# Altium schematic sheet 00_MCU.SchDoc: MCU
size A3; Date: 3/31/2015; Author: P.A.; CompanyName: STMicroelectronics; Organization: Microcontrollers Division; Address1: 12, Rue Jules HOROWITZ; Address2: 38019 Grenoble; Address3: FRANCE; DocumentNumber: 3; Revision: E-01; SheetNumber: 3; SheetTotal: 12; Project: STM32F413H-DISCO
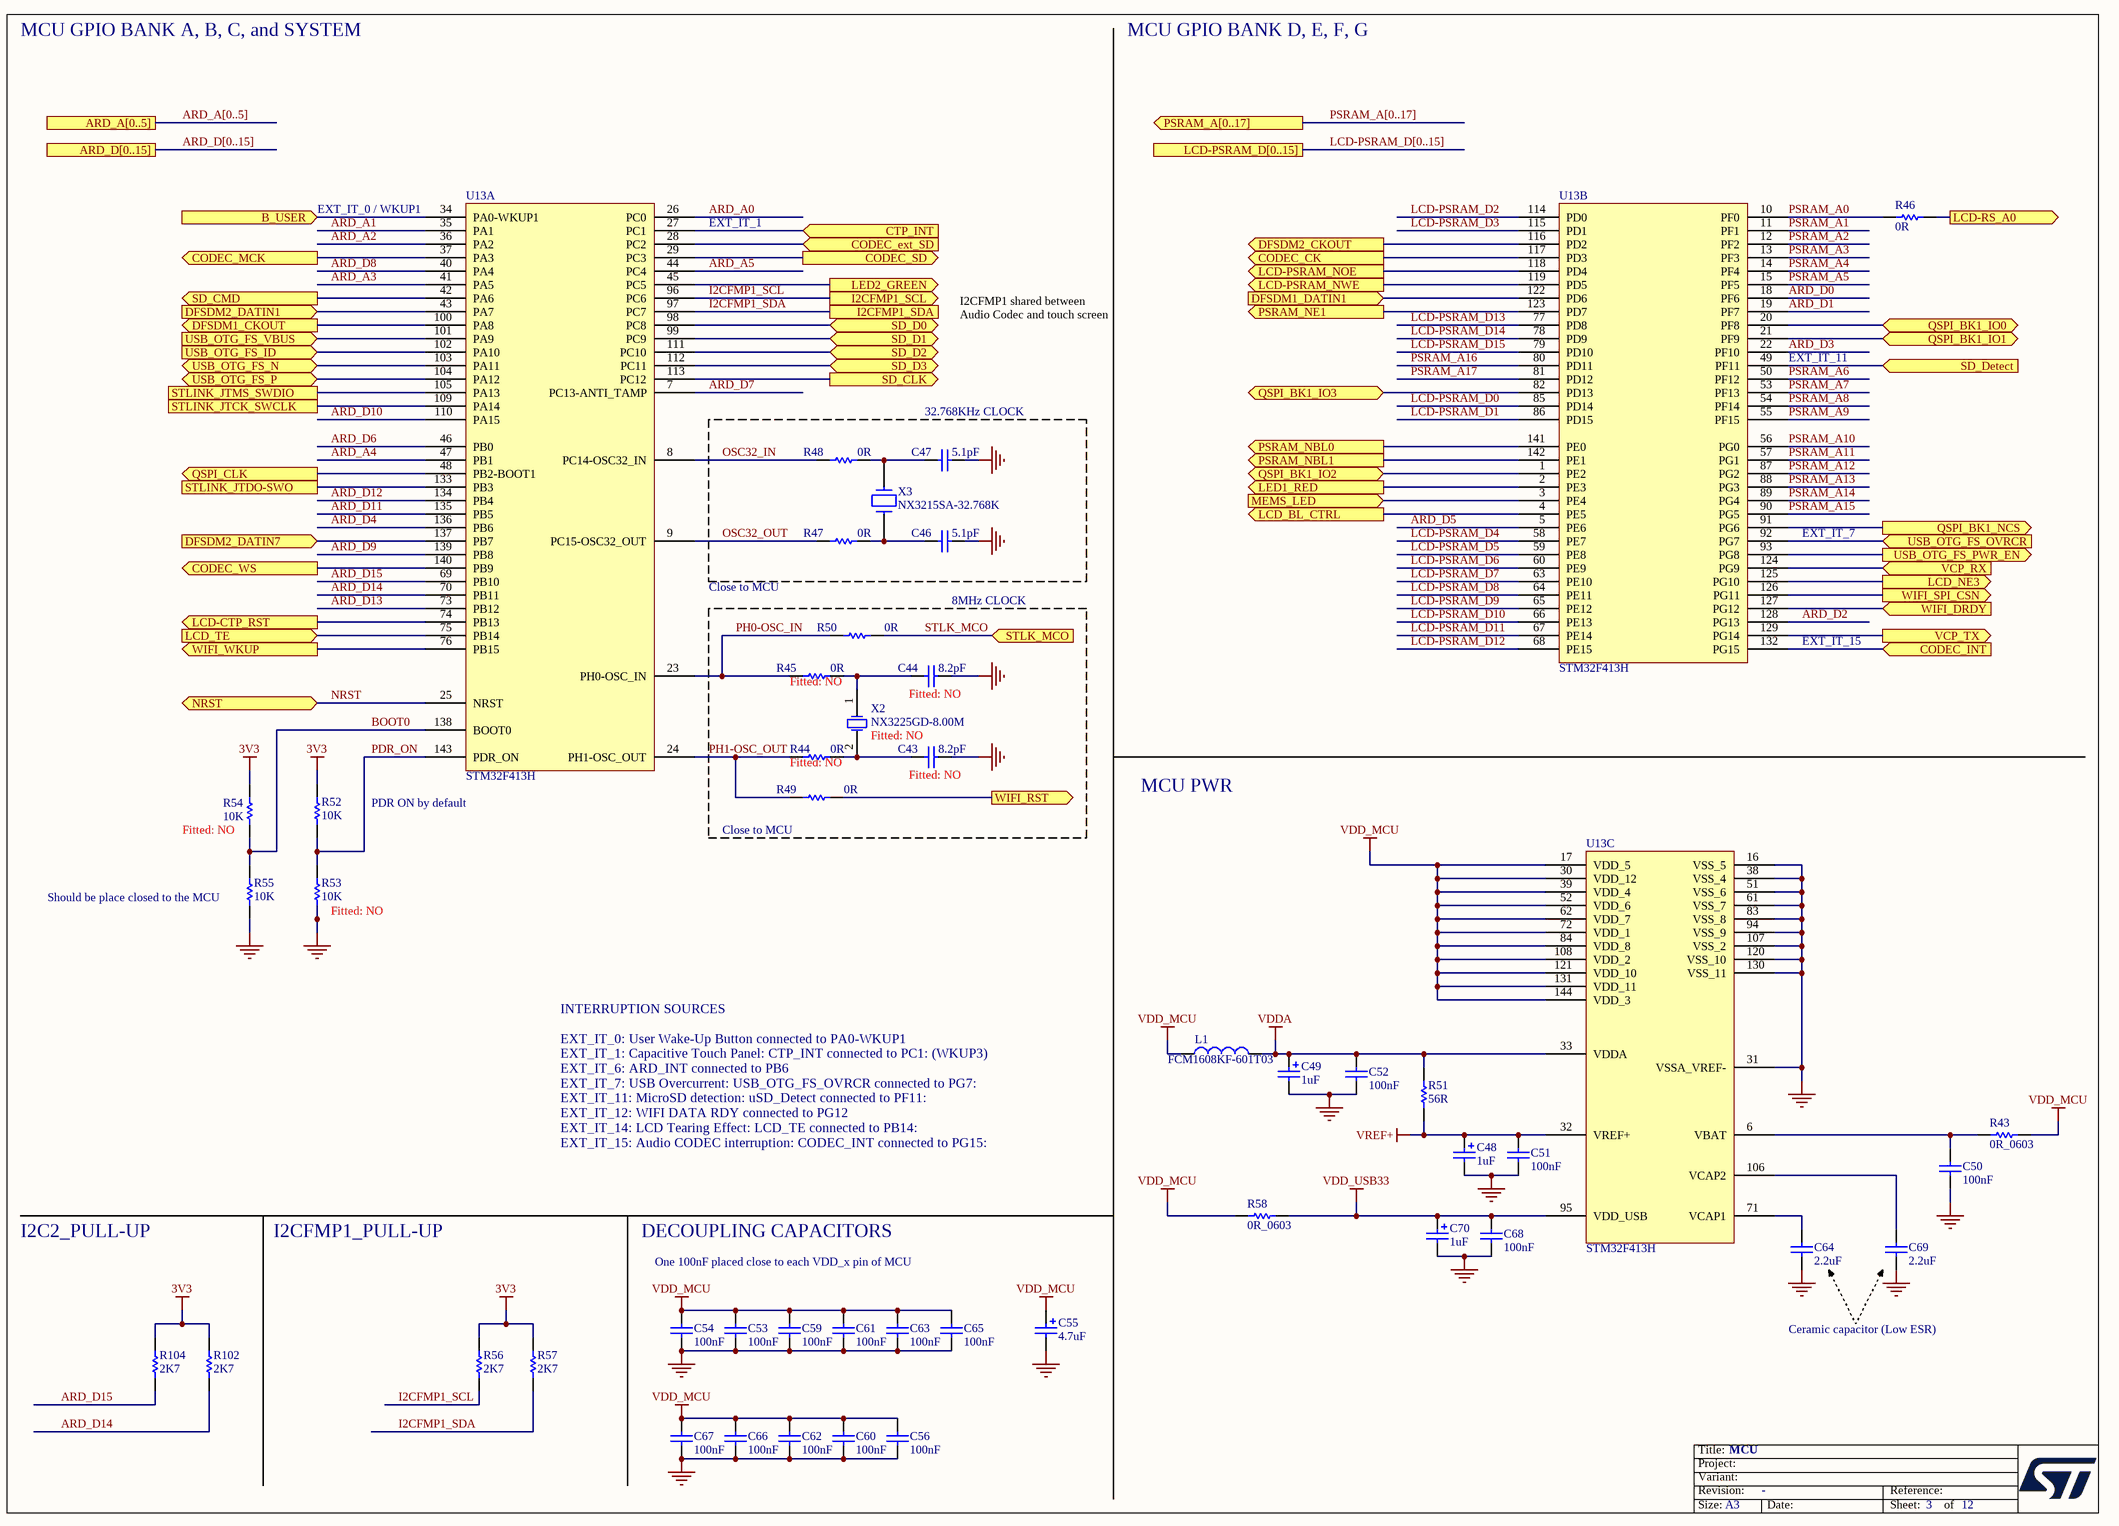
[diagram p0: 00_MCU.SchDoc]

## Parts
C43  8.2pF  Fitted: NO  [C0402]
C44  8.2pF  Fitted: NO  [C0402]
C46  5.1pF  [C0402]
C47  5.1pF  [C0402]
C48  1uF  [CPOL_TAJ-A_1206_H180]
C49  1uF  [CPOL_TAJ-A_1206_H180]
C50  100nF  [C0402]
C51  100nF  [C0402]
C52  100nF  [C0402]
C53  100nF  [C0402]
C54  100nF  [C0402]
C55  4.7uF  [CPOL_TAJ-A_1206_H180]
C56  100nF  [C0402]
C59  100nF  [C0402]
C60  100nF  [C0402]
C61  100nF  [C0402]
C62  100nF  [C0402]
C63  100nF  [C0402]
C64  2.2uF  [C1206]
C65  100nF  [C0402]
C66  100nF  [C0402]
C67  100nF  [C0402]
C68  100nF  [C0402]
C69  2.2uF  [C1206]
C70  1uF  [CPOL_TAJ-A_1206_H180]
L1  Manuf_Part_1: FCM1608KF-601T03  [L0603]  (hidden comment: 100uH)
R43  0R_0603  [R0603]
R44  0R  Fitted: NO  [R0402]
R45  0R  Fitted: NO  [R0402]
R46  0R  [R0402]
R47  0R  [R0402]
R48  0R  [R0402]
R49  0R  [R0402]
R50  0R  [R0402]
R51  56R  [R0402]
R52  10K  [R0402]
R53  10K  Fitted: NO  [R0402]
R54  10K  Fitted: NO  [R0402]
R55  10K  [R0402]
R56  2K7  [R0402]
R57  2K7  [R0402]
R58  0R_0603  [R0603]
R102  2K7  [R0402]
R104  2K7  [R0402]
U13  STM32F413H  [ICC_LQFP144_20X20_P050]  (parts A,B,C of 3)
X2  NX3225GD-8.00M  Fitted: NO  [CRY_NX3225GD_2P]
X3  NX3215SA-32.768K  [CRY_NX3215SA_2P]

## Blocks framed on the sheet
32.768KHz CLOCK: C46 C47 R47 R48 X3

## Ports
ARD_A[0..5], ARD_D[0..15], B_USER (in), CODEC_CK (out), CODEC_ext_SD (in), CODEC_INT (in), CODEC_MCK (out), CODEC_SD (out), CODEC_WS (out), CTP_INT (in), DFSDM1_CKOUT (out), DFSDM1_DATIN1 (in), DFSDM2_CKOUT (out), DFSDM2_DATIN1 (in), DFSDM2_DATIN7 (in), I2CFMP1_SCL (out), I2CFMP1_SDA, LCD-CTP_RST (out), LCD-PSRAM_D[0..15], LCD-PSRAM_NOE (out), LCD-PSRAM_NWE (out), LCD-RS_A0 (out), LCD_BL_CTRL (out), LCD_NE3 (out), LCD_TE (in), LED1_RED (out), LED2_GREEN (out), MEMS_LED (in), NRST (bidir), PSRAM_A[0..17] (out), PSRAM_NBL0 (out), PSRAM_NBL1 (out), PSRAM_NE1 (out), QSPI_BK1_IO0 (bidir), QSPI_BK1_IO1 (bidir), QSPI_BK1_IO2 (bidir), QSPI_BK1_IO3 (bidir), QSPI_BK1_NCS (out), QSPI_CLK (out), SD_CLK (out), SD_CMD (out), SD_D0 (bidir), SD_D1 (bidir), SD_D2 (bidir), SD_D3 (bidir), SD_Detect (in), STLINK_JTCK_SWCLK, STLINK_JTDO-SWO, STLINK_JTMS_SWDIO, STLK_MCO (in), USB_OTG_FS_ID (in), USB_OTG_FS_N (bidir), USB_OTG_FS_OVRCR (in), USB_OTG_FS_P (bidir), USB_OTG_FS_PWR_EN (out), USB_OTG_FS_VBUS (in), VCP_RX (in), VCP_TX (out), WIFI_DRDY (in), WIFI_RST (out), WIFI_SPI_CSN (out), WIFI_WKUP (out)

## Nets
3V3: R52.2 R54.1 R56.2 R57.2 R102.2 R104.2
GND: C43.2 C44.2 C46.2 C47.2 C48.2 C49.2 C50.1 C51.1 C52.1 C53.1 C54.1 C55.2 C56.1 C59.1 C60.1 C61.1 C62.1 C63.1 C64.1 C65.1 C66.1 C67.1 C68.1 C69.1 C70.2 R53.1 R55.1 U13.16(VSS_5) U13.31(VSSA_VREF-) U13.38(VSS_4) U13.51(VSS_6) U13.61(VSS_7) U13.83(VSS_8) U13.94(VSS_9) U13.107(VSS_2) U13.120(VSS_10) U13.130(VSS_11)
VDD_MCU: C53.2 C54.2 C55.1 C56.2 C59.2 C60.2 C61.2 C62.2 C63.2 C65.2 C66.2 C67.2 L1.1 R43.2 R58.1 U13.17(VDD_5) U13.30(VDD_12) U13.39(VDD_4) U13.52(VDD_6) U13.62(VDD_7) U13.72(VDD_1) U13.84(VDD_8) U13.108(VDD_2) U13.121(VDD_10) U13.131(VDD_11) U13.144(VDD_3)
VDD_USB33: C68.2 C70.1 R58.2 U13.95(VDD_USB)
VDDA: C49.1 C52.2 L1.2 R51.2 U13.33(VDDA)
VREF+: C48.1 C51.2 R51.1 U13.32(VREF+)
ARD_A0: U13.26(PC0)
ARD_A1: U13.35(PA1)
ARD_A2: U13.36(PA2)
ARD_A3: U13.41(PA5)
ARD_A4: U13.47(PB1)
ARD_A5: U13.44(PC4)
ARD_D0: U13.18(PF6)
ARD_D1: U13.19(PF7)
ARD_D2: U13.128(PG13)
ARD_D3: U13.22(PF10)
ARD_D4: U13.136(PB6)
ARD_D5: U13.5(PE6)
ARD_D6: U13.46(PB0)
ARD_D7: U13.7(PC13-ANTI_TAMP)
ARD_D8: U13.40(PA4)
ARD_D9: U13.139(PB8)
ARD_D10: U13.110(PA15)
ARD_D11: U13.135(PB5)
ARD_D12: U13.134(PB4)
ARD_D13: U13.73(PB12)
ARD_D14: R102.1 U13.70(PB11)
ARD_D15: R104.1 U13.69(PB10)
B_USER: U13.34(PA0-WKUP1) ; port B_USER
BOOT0: R54.2 R55.2 U13.138(BOOT0)
CODEC_CK: U13.117(PD3) ; port CODEC_CK
CODEC_ext_SD: U13.28(PC2) ; port CODEC_ext_SD
CODEC_INT: U13.132(PG15) ; port CODEC_INT
CODEC_MCK: U13.37(PA3) ; port CODEC_MCK
CODEC_SD: U13.29(PC3) ; port CODEC_SD
CODEC_WS: U13.140(PB9) ; port CODEC_WS
CTP_INT: U13.27(PC1) ; port CTP_INT
DFSDM1_CKOUT: U13.100(PA8) ; port DFSDM1_CKOUT
DFSDM1_DATIN1: U13.122(PD6) ; port DFSDM1_DATIN1
DFSDM2_CKOUT: U13.116(PD2) ; port DFSDM2_CKOUT
DFSDM2_DATIN1: U13.43(PA7) ; port DFSDM2_DATIN1
DFSDM2_DATIN7: U13.137(PB7) ; port DFSDM2_DATIN7
I2CFMP1_SCL: R56.1 U13.96(PC6) ; port I2CFMP1_SCL
I2CFMP1_SDA: R57.1 U13.97(PC7) ; port I2CFMP1_SDA
LCD-CTP_RST: U13.74(PB13) ; port LCD-CTP_RST
LCD-PSRAM_D0: U13.85(PD14)
LCD-PSRAM_D1: U13.86(PD15)
LCD-PSRAM_D2: U13.114(PD0)
LCD-PSRAM_D3: U13.115(PD1)
LCD-PSRAM_D4: U13.58(PE7)
LCD-PSRAM_D5: U13.59(PE8)
LCD-PSRAM_D6: U13.60(PE9)
LCD-PSRAM_D7: U13.63(PE10)
LCD-PSRAM_D8: U13.64(PE11)
LCD-PSRAM_D9: U13.65(PE12)
LCD-PSRAM_D10: U13.66(PE13)
LCD-PSRAM_D11: U13.67(PE14)
LCD-PSRAM_D12: U13.68(PE15)
LCD-PSRAM_D13: U13.77(PD8)
LCD-PSRAM_D14: U13.78(PD9)
LCD-PSRAM_D15: U13.79(PD10)
LCD-PSRAM_NOE: U13.118(PD4) ; port LCD-PSRAM_NOE
LCD-PSRAM_NWE: U13.119(PD5) ; port LCD-PSRAM_NWE
LCD-RS_A0: R46.2 ; port LCD-RS_A0
LCD_BL_CTRL: U13.4(PE5) ; port LCD_BL_CTRL
LCD_NE3: U13.125(PG10) ; port LCD_NE3
LCD_TE: U13.75(PB14) ; port LCD_TE
LED1_RED: U13.2(PE3) ; port LED1_RED
LED2_GREEN: U13.45(PC5) ; port LED2_GREEN
MEMS_LED: U13.3(PE4) ; port MEMS_LED
NRST: U13.25(NRST) ; port NRST
OSC32_IN: R48.1 U13.8(PC14-OSC32_IN)
OSC32_OUT: R47.1 U13.9(PC15-OSC32_OUT)
PDR_ON: R52.1 R53.2 U13.143(PDR_ON)
PH0-OSC_IN: R45.1 R50.1 U13.23(PH0-OSC_IN)
PH1-OSC_OUT: R44.1 R49.1 U13.24(PH1-OSC_OUT)
PSRAM_A0: R46.1 U13.10(PF0)
PSRAM_A1: U13.11(PF1)
PSRAM_A2: U13.12(PF2)
PSRAM_A3: U13.13(PF3)
PSRAM_A4: U13.14(PF4)
PSRAM_A5: U13.15(PF5)
PSRAM_A6: U13.50(PF12)
PSRAM_A7: U13.53(PF13)
PSRAM_A8: U13.54(PF14)
PSRAM_A9: U13.55(PF15)
PSRAM_A10: U13.56(PG0)
PSRAM_A11: U13.57(PG1)
PSRAM_A12: U13.87(PG2)
PSRAM_A13: U13.88(PG3)
PSRAM_A14: U13.89(PG4)
PSRAM_A15: U13.90(PG5)
PSRAM_A16: U13.80(PD11)
PSRAM_A17: U13.81(PD12)
PSRAM_NBL0: U13.141(PE0) ; port PSRAM_NBL0
PSRAM_NBL1: U13.142(PE1) ; port PSRAM_NBL1
PSRAM_NE1: U13.123(PD7) ; port PSRAM_NE1
QSPI_BK1_IO0: U13.20(PF8) ; port QSPI_BK1_IO0
QSPI_BK1_IO1: U13.21(PF9) ; port QSPI_BK1_IO1
QSPI_BK1_IO2: U13.1(PE2) ; port QSPI_BK1_IO2
QSPI_BK1_IO3: U13.82(PD13) ; port QSPI_BK1_IO3
QSPI_BK1_NCS: U13.91(PG6) ; port QSPI_BK1_NCS
QSPI_CLK: U13.48(PB2-BOOT1) ; port QSPI_CLK
SD_CLK: U13.113(PC12) ; port SD_CLK
SD_CMD: U13.42(PA6) ; port SD_CMD
SD_D0: U13.98(PC8) ; port SD_D0
SD_D1: U13.99(PC9) ; port SD_D1
SD_D2: U13.111(PC10) ; port SD_D2
SD_D3: U13.112(PC11) ; port SD_D3
SD_Detect: U13.49(PF11) ; port SD_Detect
STLINK_JTCK_SWCLK: U13.109(PA14) ; port STLINK_JTCK_SWCLK
STLINK_JTDO-SWO: U13.133(PB3) ; port STLINK_JTDO-SWO
STLINK_JTMS_SWDIO: U13.105(PA13) ; port STLINK_JTMS_SWDIO
STLK_MCO: R50.2 ; port STLK_MCO
USB_OTG_FS_ID: U13.102(PA10) ; port USB_OTG_FS_ID
USB_OTG_FS_N: U13.103(PA11) ; port USB_OTG_FS_N
USB_OTG_FS_OVRCR: U13.92(PG7) ; port USB_OTG_FS_OVRCR
USB_OTG_FS_P: U13.104(PA12) ; port USB_OTG_FS_P
USB_OTG_FS_PWR_EN: U13.93(PG8) ; port USB_OTG_FS_PWR_EN
USB_OTG_FS_VBUS: U13.101(PA9) ; port USB_OTG_FS_VBUS
VCP_RX: U13.124(PG9) ; port VCP_RX
VCP_TX: U13.129(PG14) ; port VCP_TX
WIFI_DRDY: U13.127(PG12) ; port WIFI_DRDY
WIFI_RST: R49.2 ; port WIFI_RST
WIFI_SPI_CSN: U13.126(PG11) ; port WIFI_SPI_CSN
WIFI_WKUP: U13.76(PB15) ; port WIFI_WKUP
NetC43_1: C43.1 R44.2 X2.2(OSC2)
NetC44_1: C44.1 R45.2 X2.1(OSC1)
NetC46_1: C46.1 R47.2 X3.2
NetC47_1: C47.1 R48.2 X3.1
NetC50_2: C50.2 R43.1 U13.6(VBAT)
NetC64_2: C64.2 U13.71(VCAP1)
NetC69_2: C69.2 U13.106(VCAP2)

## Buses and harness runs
bus ARD_A[0..5] = port ARD_A[0..5]
bus ARD_D[0..15] = port ARD_D[0..15]
bus LCD-PSRAM_D[0..15] = port LCD-PSRAM_D[0..15]
bus PSRAM_A[0..17] = port PSRAM_A[0..17]

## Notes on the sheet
- MCU GPIO BANK A, B, C, and SYSTEM
- MCU GPIO BANK D, E, F, G
- (near U13) EXT_IT_0 / WKUP1
- EXT_IT_1
- I2CFMP1 shared between
  Audio Codec and touch screen
- (near U13) EXT_IT_11
- Close to MCU
- EXT_IT_7
- 8MHz CLOCK
- EXT_IT_15
- MCU PWR
- PDR ON by default
- (near R49) Close to MCU
- (near R55) Should be place closed to the MCU
- INTERRUPTION SOURCES
  EXT_IT_0: User Wake-Up Button connected to PA0-WKUP1
  EXT_IT_1: Capacitive Touch Panel: CTP_INT connected to PC1: (WKUP3)
  EXT_IT_6: ARD_INT connected to PB6
  EXT_IT_7: USB Overcurrent: USB_OTG_FS_OVRCR connected to PG7:
  EXT_IT_11: MicroSD detection: uSD_Detect connected to PF11:
  EXT_IT_12: WIFI DATA RDY connected to PG12
  EXT_IT_14: LCD Tearing Effect: LCD_TE connected to PB14:
  EXT_IT_15: Audio CODEC interruption: CODEC_INT connected to PG15:
- I2C2_PULL-UP
- I2CFMP1_PULL-UP
- DECOUPLING CAPACITORS
- One 100nF placed close to each VDD_x pin of MCU
- Ceramic capacitor (Low ESR)

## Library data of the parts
C43 C44 = Cap_8.2pF_NPO_4%_0402: Capacitor,8.2pF,50V,NPO,4%,0402,AVX; Manuf_Part_1: 04025A8R2CAT2A; Ordered_By: Subcon
C46 C47 = Cap_5.1pF_NPO_-+0.25pF_0402: Capacitor, 5.1pF, 50V, NPO, -+0.25pF, 0402, YAGEO; Manuf_Part_1: CC0402CRNPO9BN5R1; Fitted: YES; Order_code: 311-1633-2-ND; Ordered_By: Subcon
C48 C49 C70 = Cap_1uF_POL_10%_TANA: Polarized Capacitor,1uF,16V,10%,typeA,AVX; Manuf_Part_1: TAJA105K016R; Fitted: YES; Ordered_By: Subcon
C50-C54 C56 C59-C63 C65-C68 = Cap_100nF_X7R_10%_0402: Capacitor,100nF,16V,X7R,10%,0402,YAGEO; Manuf_Part_1: CC0402KRX7R7BB104; Fitted: YES; Ordered_By: Subcon
C55 = Cap_4.7uF_POL_10%_TANA: Polarized Capacitor,4.7uF,16V,10%,typeA,AVX; Manuf_Part_1: TAJA475K016R; Fitted: YES; Ordered_By: Subcon
C64 C69 = Cap_2.2uF_X7R_10%_1206: Capacitor,2.2uF,16V, X7R,10%,1206,YAGEO; Manuf_Part_1: CC1206KKX7R7BB225; Manuf_Part_2: C1206C225K4RAC; Manuf_2: KEMET; Fitted: YES; Ordered_By: Subcon
L1 = BEAD_600R_350MA_0603: Bead,600R,350mA,0603; Manuf_2: TDK; Manuf_Part_2: MPZ1608S300A; Manuf_1: Tai-tech; Manuf_Part_3: BLM18PG121SN1D; Manuf_3: MURATA; Fitted: YES; Ordered_By: Subcon
R43 R58 = Res_0_5%_0603: Resistor,0R,0603,5%,YAGEO; Manuf_Part_1: RC0603JR-070RL; Fitted: YES; Order_Code: 2363481; Ordered_By: subcon
R44 R45 = Res_0_5%_0402: Resistor,0R,0402,5%,YAGEO; Manuf_Part_1: RC0402JR-070RL; Order_Code: 2363467; Ordered_By: Subcon
R46-R48 R50 = Res_0_5%_0402: Resistor,0R,0402,5%,YAGEO; Manuf_Part_1: RC0402JR-070RL; Fitted: YES; Order_Code: 2363467; Ordered_By: Subcon
R49 = Res_0_5%_0402: Resistor,0R,0402,5%,YAGEO; Manuf_Part_1: RC0402JR-070RL; Order_Code: 2363467; Fitted: YES; Ordered_By: Subcon
R51 = Res_56_1%_0402: Resistor,56R,0402,1%,YAGEO; Manuf_Part_1: RC0402FR-0756RL; Fitted: YES; Order_Code: 9239081RL; Ordered_By: Subcon
R52 R55 = Res_10K_1%_0402: Resistor,10K,0402,1%,YAGEO; Manuf_Part_1: RC0402FR-0710KL; Fitted: YES; Ordered_By: subcon
R53 R54 = Res_10K_1%_0402: Resistor,10K,0402,1%,YAGEO; Manuf_Part_1: RC0402FR-0710KL; Ordered_By: subcon
R56 R57 R102 R104 = Res_2K7_1%_0402: Resistor,2K7,0402,1%,YAGEO; Manuf_Part_1: RC0402FR-072K7L; Fitted: YES; Ordered_By: Subcon
U13 = STM32F413ZHT6U: STM32 Tiny Manta 1M5 LQFP144 (STM32F413ZHT6U); Manuf_1: STM; Ref St: 9175122; ECCN_US/EU: 3A991A2/NEC; Fitted: YES
X2 = XTAL_8M_NX3225GD: Crystal 8Mhz, 8pF, -+50PPM, SMD; Manuf_1: NDK; Manuf_Part_1: NX3225GD 8MHz EXS00A-CG04874; ECCN_US/EU: EAR99/NEC; NDK Ref: X3127326; Ref St: 9157029; Ordered_By: STM
X3 = XTAL_32K_NX3215SA: Crystal 32.768kHz, 6pF, -+20PPM, R=50K, SMD; Manuf_1: NDK; Manuf_Part_1: NX3215SA 32.768KHz EXS00A-MU00525; ECCN_US/EU: EAR99/NEC; Ref St: 9157034; NDK Ref: X3101802; Fitted: YES; Ordered_By: STM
